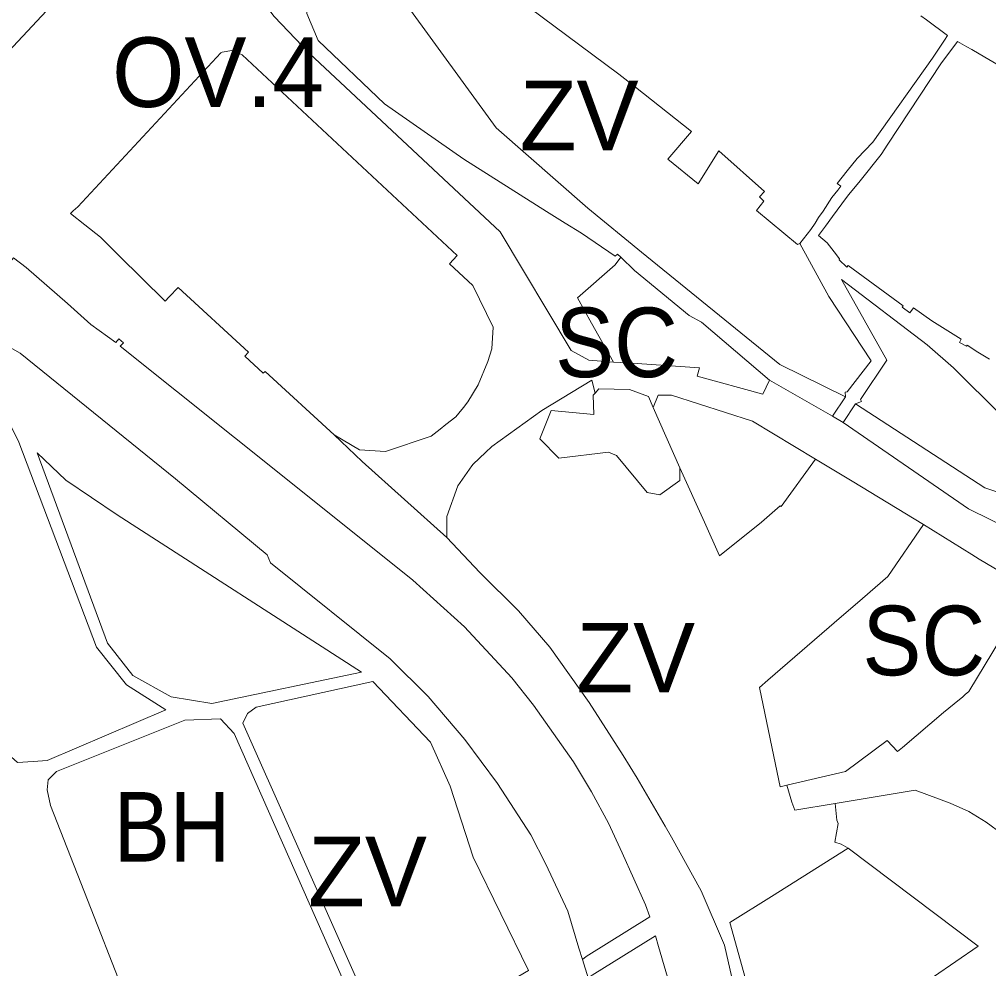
# Model space of a CAD drawing. Extents: x -650451 to -642268, y -1075216 to -1066610.
# Drawn here: x -647355.8 to -647188.6, y -1070735.3 to -1070571.6 of the extents above; entities that cross this region are included whole.
import ezdxf

# ---------------------------------------------------------------- set-up
doc = ezdxf.new("R2010")
doc.units = 0
doc.header["$LTSCALE"] = 4.8
for name, color, linetype, lineweight in [('1', 7, 'Continuous', 13), ('11', 7, 'Continuous', 13), ('15', 7, 'Continuous', 13), ('17', 7, 'Continuous', 13), ('2', 7, 'Continuous', 13), ('40', 7, 'Continuous', 13), ('45', 7, 'Continuous', 13)]:
    doc.layers.add(name, color=color, linetype=linetype, lineweight=lineweight)
doc.layers.add('62', color=7, linetype='Continuous')

msp = doc.modelspace()

# ---------------------------------------------------------------- linework, layer by layer
at = {"layer": '1'}
for points in [[(-647353.37, -1070699.58), (-647356.11, -1070699.76), (-647358.85, -1070697.3), (-647362.45, -1070687.53), (-647369.09, -1070669.52), (-647370.33, -1070666.14), (-647379.3, -1070641.82), (-647378.23, -1070639.17), (-647370.09, -1070629.34), (-647364.48, -1070631.56), (-647359.71, -1070636.82), (-647355.84, -1070644.52), (-647342.44, -1070679.87), (-647337.28, -1070686.33), (-647330.49, -1070690.64), (-647350.95, -1070699.42)], [(-647325.77, -1070770.02), (-647333.28, -1070750.85), (-647334.71, -1070747.19), (-647340.28, -1070732.97), (-647341.72, -1070729.31), (-647350.4, -1070707.16), (-647350.96, -1070704.48), (-647350.8, -1070702.71), (-647349.38, -1070701.29), (-647327.26, -1070692.44), (-647321.09, -1070692.24), (-647318.75, -1070694.72), (-647293.92, -1070750.76)]]:
    msp.add_lwpolyline(points, close=True, dxfattribs=at)
at = {"layer": '11'}
msp.add_lwpolyline([(-647301.47, -1070643.27), (-647313.38, -1070632.31), (-647313.74, -1070632.63), (-647316.87, -1070629.7), (-647316.23, -1070629), (-647328.38, -1070617.87), (-647329.91, -1070619.43), (-647330.65, -1070620.18), (-647338.62, -1070612.33), (-647341.79, -1070609.17), (-647344.5, -1070607.02), (-647346.97, -1070605.07), (-647346.47, -1070604.63), (-647345.68, -1070603.93), (-647321.05, -1070577.4), (-647320.8, -1070577.25), (-647319.1, -1070576.96), (-647318.73, -1070577.12), (-647317.37, -1070577.72), (-647280.26, -1070612.31), (-647281.56, -1070613.76), (-647277.55, -1070617.48), (-647274.07, -1070624.66), (-647274.29, -1070628.4), (-647274.95, -1070630.6), (-647276.66, -1070634.6), (-647278.41, -1070637.55), (-647279.19, -1070638.53), (-647279.99, -1070639.53), (-647280.48, -1070640.15), (-647282.2, -1070641.48), (-647283.2, -1070642.26), (-647284.76, -1070643.47), (-647292.63, -1070646.15), (-647297.09, -1070645.85)], close=True, dxfattribs=at)
for points in [[(-647223.41, -1070703.66), (-647213.3, -1070701.31), (-647206.09, -1070695.93), (-647204.33, -1070697.84), (-647203.49, -1070697.13), (-647196.38, -1070691.15), (-647194.55, -1070689.63), (-647193.07, -1070688.41), (-647192.66, -1070688.03), (-647192.05, -1070687.52), (-647190.53, -1070685.01), (-647188.06, -1070680.95), (-647186.61, -1070678.56), (-647183.3, -1070673.12), (-647181.36, -1070669.94)], [(-647215.09, -1070706.81), (-647222.02, -1070707.98), (-647222.52, -1070706.56), (-647223.41, -1070703.66)], [(-647186.24, -1070712.1), (-647189.06, -1070710.05), (-647192.01, -1070708.17), (-647195.23, -1070706.78), (-647201.28, -1070704.5), (-647215.09, -1070706.81)]]:
    msp.add_lwpolyline(points, dxfattribs=at)
at = {"layer": '15'}
for points in [[(-647359.36, -1070578.94), (-647344.52, -1070563.09), (-647344.36, -1070562.93), (-647343.66, -1070563.58), (-647336.29, -1070555.75), (-647335.69, -1070555.11), (-647336, -1070554.26), (-647346.61, -1070524.59), (-647351.57, -1070510.89), (-647356.57, -1070496.88)], [(-647312.46, -1070553.28), (-647317.15, -1070558.53), (-647317.82, -1070560.19), (-647317.54, -1070562.38), (-647317.15, -1070563.76), (-647315.54, -1070566.13), (-647311.82, -1070571.13), (-647305.74, -1070577.49), (-647272.84, -1070608.27), (-647260.63, -1070628.71), (-647257.54, -1070630.35), (-647253.3, -1070630.72)], [(-647221.14, -1070610.26), (-647219.29, -1070607.85), (-647218.53, -1070606.74), (-647217.96, -1070605.79), (-647217.17, -1070604.69), (-647215.63, -1070602.35), (-647214.6, -1070601.09), (-647214.11, -1070600.39), (-647214.72, -1070599.93), (-647212.98, -1070597.76), (-647211.27, -1070595.62), (-647208.55, -1070592.81), (-647198.31, -1070578.28), (-647196.23, -1070575.2), (-647195.7, -1070574.42), (-647199.34, -1070571.72), (-647200.3, -1070571.01)], [(-647185.4, -1070580.35), (-647189.29, -1070578.11), (-647191.52, -1070576.82), (-647192.34, -1070576.35), (-647193.96, -1070575.45), (-647196.84, -1070579.31), (-647205.98, -1070593.12), (-647207.14, -1070594.94), (-647210.79, -1070599.46), (-647212.69, -1070601.8), (-647213.13, -1070602.35), (-647215.54, -1070605.62), (-647216.75, -1070607.27), (-647217.95, -1070608.9), (-647216.43, -1070610.17), (-647215.24, -1070611.71), (-647214.33, -1070612.9), (-647214.39, -1070613.09), (-647213.05, -1070614.33), (-647212.85, -1070614.07), (-647203.32, -1070620.99), (-647203.51, -1070621.22), (-647202.2, -1070622.2), (-647201.54, -1070621.37), (-647198.43, -1070623.59), (-647193.35, -1070626.75), (-647193.61, -1070627.33), (-647192.44, -1070627.96), (-647192.3, -1070627.78), (-647190.45, -1070628.98), (-647188.43, -1070630.2)], [(-647213.29, -1070636.7), (-647213.37, -1070635.89), (-647213, -1070635.85), (-647208.87, -1070630.47), (-647216.16, -1070619.38), (-647221.14, -1070610.26)], [(-647356.77, -1070612.71), (-647364.72, -1070622.59), (-647357.74, -1070627.98), (-647355.61, -1070629.17), (-647328.85, -1070650.84), (-647313.05, -1070663.93), (-647312.47, -1070665.3), (-647291.8, -1070681.86), (-647285.28, -1070688.36), (-647278.93, -1070695.8), (-647273.3, -1070703.37), (-647267.58, -1070712.21), (-647264.99, -1070717.25), (-647261.17, -1070725.4), (-647259.26, -1070731.73), (-647258.66, -1070733.71), (-647257.7, -1070736.849)], [(-647258.66, -1070733.71), (-647258.02, -1070733.2), (-647247.02, -1070726.38), (-647247.76, -1070724.31), (-647251.79, -1070715.3), (-647254.17, -1070710.2), (-647257.09, -1070704.81), (-647260.2, -1070699.65), (-647267.08, -1070689.85), (-647270.82, -1070685.13), (-647278.98, -1070676.34), (-647287.92, -1070668.32), (-647308.93, -1070651.44), (-647338.37, -1070627.96), (-647337.81, -1070627.4), (-647338.61, -1070626.72), (-647339.15, -1070627.35), (-647343.45, -1070624.25), (-647347.45, -1070620.61), (-647354.58, -1070614.42), (-647356.77, -1070612.71)], [(-647170.16, -1070644.59), (-647172.63, -1070643.88), (-647186.4, -1070639.91), (-647194.67, -1070631.67), (-647199.19, -1070627.76), (-647213.98, -1070616.48), (-647206.19, -1070630.4), (-647210.68, -1070637.17), (-647210.52, -1070637.52), (-647211.57, -1070637.9), (-647213.68, -1070641.13), (-647215.55, -1070640.03), (-647213.29, -1070636.7)], [(-647253.3, -1070630.72), (-647250.87, -1070630.83), (-647238.45, -1070631.69), (-647238.85, -1070633.11), (-647227.54, -1070636.24), (-647226.39, -1070633.82), (-647215.55, -1070640.03), (-647213.68, -1070641.13)], [(-647256.46, -1070636.04), (-647257.03, -1070633.8), (-647265.65, -1070639.04), (-647274.26, -1070645.27), (-647275.35, -1070646.3), (-647277.51, -1070648.32), (-647277.72, -1070648.62), (-647280.13, -1070652.04), (-647282.03, -1070657.35), (-647282.03, -1070660.97)], [(-647246.49, -1070638.53), (-647247.27, -1070636.62), (-647250.55, -1070635.45), (-647255.81, -1070635.34), (-647256.46, -1070636.04)], [(-647218.44, -1070647.43), (-647229.34, -1070640.91), (-647243.28, -1070636.43), (-647245.6, -1070636.4), (-647246.49, -1070638.53)], [(-647213.68, -1070641.13), (-647192.07, -1070655.98), (-647168.72, -1070667.48), (-647167.98, -1070665.84), (-647155.28, -1070670.24), (-647153.1, -1070667.29), (-647148.15, -1070669.49), (-647150.25, -1070671.84)], [(-647282.03, -1070660.97), (-647296.63, -1070647.83), (-647301.47, -1070643.27)], [(-647301.47, -1070643.27), (-647296.63, -1070647.83), (-647282.03, -1070660.97)], [(-647199.86, -1070658.73), (-647212.15, -1070651.26), (-647218.44, -1070647.43)], [(-647181.36, -1070669.94), (-647184.22, -1070668.24), (-647190.22, -1070664.68), (-647191.53, -1070663.9), (-647199.86, -1070658.73)], [(-647282.03, -1070660.97), (-647276.33, -1070666.98), (-647269.7, -1070673.6), (-647264.28, -1070679.85), (-647257.5, -1070689.42), (-647251.65, -1070698.54), (-647249.24, -1070702.45), (-647244.42, -1070710.72), (-647243.32, -1070712.61), (-647238.17, -1070721.85), (-647234.15, -1070731.23), (-647232.04, -1070740.63), (-647230.91, -1070759.64), (-647232.98, -1070796.15)], [(-647234.692, -1070915.011), (-647224.85, -1070903.83), (-647230.18, -1070895.42), (-647234.96, -1070886.44), (-647239.25, -1070875.22), (-647242.25, -1070862.17), (-647243.66, -1070845.66), (-647239.62, -1070773.47), (-647239.86, -1070761.48), (-647241.3, -1070749.53), (-647241.85, -1070745.57), (-647240.98, -1070745.38), (-647241.85, -1070740.97), (-647242.7, -1070741.08), (-647245.52, -1070731.47), (-647246.06, -1070729.62), (-647257.01, -1070736.43), (-647257.7, -1070736.849), (-647258.66, -1070733.71)]]:
    msp.add_lwpolyline(points, dxfattribs=at)
for points in [[(-647301.47, -1070643.27), (-647297.09, -1070645.85), (-647292.63, -1070646.15), (-647284.76, -1070643.47), (-647283.2, -1070642.26), (-647282.2, -1070641.48), (-647280.48, -1070640.15), (-647279.99, -1070639.53), (-647279.19, -1070638.53), (-647278.41, -1070637.55), (-647276.66, -1070634.6), (-647274.95, -1070630.6), (-647274.29, -1070628.4), (-647274.07, -1070624.66), (-647277.55, -1070617.48), (-647281.56, -1070613.76), (-647280.26, -1070612.31), (-647317.37, -1070577.72), (-647318.73, -1070577.12), (-647319.1, -1070576.96), (-647320.8, -1070577.25), (-647321.05, -1070577.4), (-647345.68, -1070603.93), (-647346.47, -1070604.63), (-647346.97, -1070605.07), (-647344.5, -1070607.02), (-647341.79, -1070609.17), (-647338.62, -1070612.33), (-647330.65, -1070620.18), (-647329.91, -1070619.43), (-647328.38, -1070617.87), (-647316.23, -1070629), (-647316.87, -1070629.7), (-647313.74, -1070632.63), (-647313.38, -1070632.31)], [(-647353.37, -1070699.58), (-647350.95, -1070699.42), (-647330.49, -1070690.64), (-647337.28, -1070686.33), (-647342.44, -1070679.87), (-647355.84, -1070644.52), (-647359.71, -1070636.82), (-647364.48, -1070631.56), (-647370.09, -1070629.34), (-647378.23, -1070639.17), (-647379.3, -1070641.82), (-647370.33, -1070666.14), (-647369.09, -1070669.52), (-647362.45, -1070687.53), (-647358.85, -1070697.3), (-647356.11, -1070699.76)], [(-647296.74, -1070684.19), (-647338.92, -1070657.07), (-647347.73, -1070651.08), (-647352.71, -1070646.37), (-647340.54, -1070679.18), (-647336.21, -1070684.77), (-647329.61, -1070688.42), (-647322.6, -1070689.56)], [(-647267.95, -1070735.6), (-647277.48, -1070716.04), (-647281.45, -1070703.81), (-647284.89, -1070696.22), (-647294.81, -1070685.78), (-647314.95, -1070690.19), (-647316.43, -1070691.27), (-647317.24, -1070692.98), (-647291.98, -1070749.68)], [(-647325.77, -1070770.02), (-647293.92, -1070750.76), (-647318.75, -1070694.72), (-647321.09, -1070692.24), (-647327.26, -1070692.44), (-647349.38, -1070701.29), (-647350.8, -1070702.71), (-647350.96, -1070704.48), (-647350.4, -1070707.16), (-647341.72, -1070729.31), (-647340.28, -1070732.97), (-647334.71, -1070747.19), (-647333.28, -1070750.85)]]:
    msp.add_lwpolyline(points, close=True, dxfattribs=at)
at = {"layer": '17'}
for points in [[(-647356.57, -1070496.88), (-647351.57, -1070510.89), (-647346.61, -1070524.59), (-647336, -1070554.26), (-647335.69, -1070555.11), (-647336.29, -1070555.75), (-647343.66, -1070563.58), (-647344.36, -1070562.93), (-647344.52, -1070563.09), (-647359.36, -1070578.94)], [(-647221.14, -1070610.26), (-647221.58, -1070610.41), (-647228.64, -1070604.58), (-647227.36, -1070602.95), (-647228.11, -1070602.21), (-647227.29, -1070601.29), (-647235.16, -1070594.29), (-647238.73, -1070599.96), (-647243.96, -1070595.7), (-647239.85, -1070590.97), (-647249.52, -1070583.31), (-647252.39, -1070581.07), (-647274.56, -1070564.5)], [(-647200.3, -1070571.01), (-647199.34, -1070571.72), (-647195.7, -1070574.42), (-647196.23, -1070575.2), (-647198.31, -1070578.28), (-647208.55, -1070592.81), (-647211.27, -1070595.62), (-647212.98, -1070597.76), (-647214.72, -1070599.93), (-647214.11, -1070600.39), (-647214.6, -1070601.09), (-647215.63, -1070602.35), (-647217.17, -1070604.69), (-647217.96, -1070605.79), (-647218.53, -1070606.74), (-647219.29, -1070607.85), (-647221.14, -1070610.26)], [(-647188.43, -1070630.2), (-647190.45, -1070628.98), (-647192.3, -1070627.78), (-647192.44, -1070627.96), (-647193.61, -1070627.33), (-647193.35, -1070626.75), (-647198.43, -1070623.59), (-647201.54, -1070621.37), (-647202.2, -1070622.2), (-647203.51, -1070621.22), (-647203.32, -1070620.99), (-647212.85, -1070614.07), (-647213.05, -1070614.33), (-647214.39, -1070613.09), (-647214.33, -1070612.9), (-647215.24, -1070611.71), (-647216.43, -1070610.17), (-647217.95, -1070608.9), (-647216.75, -1070607.27), (-647215.54, -1070605.62), (-647213.13, -1070602.35), (-647212.69, -1070601.8), (-647210.79, -1070599.46), (-647207.14, -1070594.94), (-647205.98, -1070593.12), (-647196.84, -1070579.31), (-647193.96, -1070575.45), (-647192.34, -1070576.35), (-647191.52, -1070576.82), (-647189.29, -1070578.11), (-647185.4, -1070580.35)], [(-647253.3, -1070630.72), (-647257.07, -1070624), (-647259.53, -1070619.63), (-647253.03, -1070613.91), (-647252.04, -1070612.62)], [(-647252.04, -1070612.62), (-647249.7, -1070614.89), (-647240.25, -1070622.65), (-647238.12, -1070623.8), (-647226.39, -1070633.82)], [(-647226.39, -1070633.82), (-647227.54, -1070636.24), (-647238.85, -1070633.11), (-647238.45, -1070631.69), (-647250.87, -1070630.83), (-647253.3, -1070630.72)], [(-647246.49, -1070638.53), (-647245.6, -1070636.4), (-647243.28, -1070636.43), (-647229.34, -1070640.91), (-647218.44, -1070647.43)], [(-647218.44, -1070647.43), (-647224.37, -1070655.59), (-647224.57, -1070655.48), (-647227.76, -1070658.33), (-647235.02, -1070664.1), (-647237.61, -1070658.33), (-647241.89, -1070648.94), (-647246.49, -1070638.53)], [(-647223.41, -1070703.66), (-647224.55, -1070703.92), (-647225.35, -1070700.1), (-647228.14, -1070686.83), (-647226.67, -1070685.57), (-647213.96, -1070674.56), (-647211.22, -1070672.21), (-647210.36, -1070671.47), (-647206.02, -1070667.69), (-647199.86, -1070658.73)], [(-647199.86, -1070658.73), (-647191.53, -1070663.9), (-647190.22, -1070664.68), (-647184.22, -1070668.24), (-647181.36, -1070669.94)], [(-647181.36, -1070669.94), (-647183.3, -1070673.12), (-647186.61, -1070678.56), (-647188.06, -1070680.95), (-647190.53, -1070685.01), (-647192.05, -1070687.52), (-647192.66, -1070688.03), (-647193.07, -1070688.41), (-647194.55, -1070689.63), (-647196.38, -1070691.15), (-647203.49, -1070697.13), (-647204.33, -1070697.84), (-647206.09, -1070695.93), (-647213.3, -1070701.31), (-647223.41, -1070703.66)], [(-647215.09, -1070706.81), (-647201.28, -1070704.5), (-647195.23, -1070706.78), (-647192.01, -1070708.17), (-647189.06, -1070710.05), (-647186.24, -1070712.1)], [(-647212.86, -1070714.53), (-647214.06, -1070713.83), (-647215.15, -1070713.48), (-647214.53, -1070710.27), (-647214.8, -1070709.66), (-647215.09, -1070706.81)], [(-647236.44, -1070835.13), (-647232.78, -1070836.22), (-647211.44, -1070842.62), (-647207.55, -1070836.46), (-647212.27, -1070833.64), (-647209.5, -1070829), (-647204.6, -1070817.33), (-647201.97, -1070813.55), (-647209.67, -1070797.53), (-647200.88, -1070786.23), (-647200.9, -1070785.57), (-647198.85, -1070785.66), (-647199.54, -1070780.04), (-647199.97, -1070773.61), (-647200.04, -1070772.52), (-647199.38, -1070763.7), (-647200.89, -1070751.29), (-647202.89, -1070747.79), (-647203.21, -1070744.98), (-647206.67, -1070742.46), (-647198.12, -1070736.68), (-647190.41, -1070731.4), (-647212.86, -1070714.53)]]:
    msp.add_lwpolyline(points, dxfattribs=at)
at = {"layer": '2'}
for points in [[(-647212.86, -1070714.53), (-647190.41, -1070731.4), (-647198.12, -1070736.68), (-647206.67, -1070742.46), (-647203.21, -1070744.98), (-647202.89, -1070747.79), (-647200.89, -1070751.29), (-647199.38, -1070763.7), (-647200.04, -1070772.52), (-647199.97, -1070773.61), (-647199.54, -1070780.04), (-647198.85, -1070785.66), (-647200.9, -1070785.57), (-647200.88, -1070786.23), (-647209.67, -1070797.53), (-647201.97, -1070813.55), (-647204.6, -1070817.33), (-647209.5, -1070829), (-647212.27, -1070833.64), (-647207.55, -1070836.46), (-647211.44, -1070842.62), (-647232.78, -1070836.22), (-647236.44, -1070835.13)], [(-647232.98, -1070796.15), (-647230.79, -1070796.17), (-647230.48, -1070796.18), (-647229.81, -1070784.01), (-647229.2, -1070772.02), (-647228.38, -1070759.67), (-647227.57, -1070747.79), (-647233.26, -1070727.35), (-647226.05, -1070722.86), (-647212.86, -1070714.53)]]:
    msp.add_lwpolyline(points, dxfattribs=at)
at = {"layer": '40'}
for points in [[(-647213.29, -1070636.7), (-647224.62, -1070631.13), (-647248.47, -1070611.77), (-647257.72, -1070604.16), (-647273.54, -1070590.32), (-647289.23, -1070568.74), (-647294.04, -1070557.72), (-647299.94, -1070539.82), (-647309.17, -1070504.84)], [(-647253.3, -1070630.72), (-647257.54, -1070630.35), (-647260.63, -1070628.71), (-647272.84, -1070608.27), (-647305.74, -1070577.49), (-647311.82, -1070571.13), (-647315.54, -1070566.13), (-647317.15, -1070563.76), (-647317.54, -1070562.38), (-647317.82, -1070560.19), (-647317.15, -1070558.53), (-647312.46, -1070553.28)], [(-647312.46, -1070553.28), (-647307.04, -1070558.96), (-647306.21, -1070570.58), (-647304.24, -1070575.28), (-647292.78, -1070586.17), (-647279.11, -1070595.72), (-647264.84, -1070604.72), (-647261.65, -1070606.73), (-647258.83, -1070608.49), (-647253.03, -1070612.42), (-647252.64, -1070612.08), (-647252.04, -1070612.62)], [(-647274.56, -1070564.5), (-647252.39, -1070581.07), (-647249.52, -1070583.31), (-647239.85, -1070590.97), (-647243.96, -1070595.7), (-647238.73, -1070599.96), (-647235.16, -1070594.29), (-647227.29, -1070601.29), (-647228.11, -1070602.21), (-647227.36, -1070602.95), (-647228.64, -1070604.58), (-647221.58, -1070610.41), (-647221.14, -1070610.26)], [(-647221.14, -1070610.26), (-647216.16, -1070619.38), (-647208.87, -1070630.47), (-647213, -1070635.85), (-647213.37, -1070635.89), (-647213.29, -1070636.7)], [(-647252.04, -1070612.62), (-647253.03, -1070613.91), (-647259.53, -1070619.63), (-647257.07, -1070624), (-647253.3, -1070630.72)], [(-647211.57, -1070637.9), (-647210.52, -1070637.52), (-647210.68, -1070637.17), (-647206.19, -1070630.4), (-647213.98, -1070616.48), (-647199.19, -1070627.76), (-647194.67, -1070631.67), (-647186.4, -1070639.91), (-647172.63, -1070643.88), (-647170.16, -1070644.59)], [(-647282.03, -1070660.97), (-647282.03, -1070657.35), (-647280.13, -1070652.04), (-647277.72, -1070648.62), (-647277.51, -1070648.32), (-647275.35, -1070646.3), (-647274.26, -1070645.27), (-647265.65, -1070639.04), (-647257.03, -1070633.8), (-647256.46, -1070636.04)], [(-647256.46, -1070636.04), (-647256.83, -1070636.43), (-647256.68, -1070639.73), (-647264.03, -1070639.08), (-647265.98, -1070643.95), (-647262.73, -1070647.29), (-647254.19, -1070646.22), (-647252.77, -1070646.84), (-647247.51, -1070653.21), (-647245.29, -1070653.59), (-647241.87, -1070651.11), (-647241.89, -1070648.94)], [(-647175.83, -1070656.89), (-647189.25, -1070652.4), (-647211.57, -1070637.9)], [(-647241.89, -1070648.94), (-647237.61, -1070658.33), (-647235.02, -1070664.1), (-647227.76, -1070658.33), (-647224.57, -1070655.48), (-647224.37, -1070655.59), (-647218.44, -1070647.43)], [(-647218.44, -1070647.43), (-647212.15, -1070651.26), (-647199.86, -1070658.73)], [(-647199.86, -1070658.73), (-647206.02, -1070667.69), (-647210.36, -1070671.47), (-647211.22, -1070672.21), (-647213.96, -1070674.56), (-647226.67, -1070685.57), (-647228.14, -1070686.83), (-647225.35, -1070700.1), (-647224.55, -1070703.92), (-647223.41, -1070703.66)], [(-647232.98, -1070796.15), (-647230.91, -1070759.64), (-647232.04, -1070740.63), (-647234.15, -1070731.23), (-647238.17, -1070721.85), (-647243.32, -1070712.61), (-647244.42, -1070710.72), (-647249.24, -1070702.45), (-647251.65, -1070698.54), (-647257.5, -1070689.42), (-647264.28, -1070679.85), (-647269.7, -1070673.6), (-647276.33, -1070666.98), (-647282.03, -1070660.97)], [(-647223.41, -1070703.66), (-647222.52, -1070706.56), (-647222.02, -1070707.98), (-647215.09, -1070706.81)], [(-647215.09, -1070706.81), (-647214.8, -1070709.66), (-647214.53, -1070710.27), (-647215.15, -1070713.48), (-647214.06, -1070713.83), (-647212.86, -1070714.53)], [(-647212.86, -1070714.53), (-647226.05, -1070722.86), (-647233.26, -1070727.35), (-647227.57, -1070747.79), (-647228.38, -1070759.67), (-647229.2, -1070772.02), (-647229.81, -1070784.01), (-647230.48, -1070796.18), (-647230.79, -1070796.17), (-647232.98, -1070796.15)]]:
    msp.add_lwpolyline(points, dxfattribs=at)
for points in [[(-647296.74, -1070684.19), (-647322.6, -1070689.56), (-647329.61, -1070688.42), (-647336.21, -1070684.77), (-647340.54, -1070679.18), (-647352.71, -1070646.37), (-647347.73, -1070651.08), (-647338.92, -1070657.07)], [(-647267.95, -1070735.6), (-647291.98, -1070749.68), (-647317.24, -1070692.98), (-647316.43, -1070691.27), (-647314.95, -1070690.19), (-647294.81, -1070685.78), (-647284.89, -1070696.22), (-647281.45, -1070703.81), (-647277.48, -1070716.04)]]:
    msp.add_lwpolyline(points, close=True, dxfattribs=at)
at = {"layer": '45'}
msp.add_line((-647213.68, -1070641.13), (-647211.57, -1070637.9), dxfattribs=at)
for points in [[(-647309.17, -1070504.84), (-647299.94, -1070539.82), (-647294.04, -1070557.72), (-647289.23, -1070568.74), (-647273.54, -1070590.32), (-647257.72, -1070604.16), (-647248.47, -1070611.77), (-647224.62, -1070631.13), (-647213.29, -1070636.7), (-647215.55, -1070640.03), (-647226.39, -1070633.82)], [(-647252.04, -1070612.62), (-647252.64, -1070612.08), (-647253.03, -1070612.42), (-647258.83, -1070608.49), (-647261.65, -1070606.73), (-647264.84, -1070604.72), (-647279.11, -1070595.72), (-647292.78, -1070586.17), (-647304.24, -1070575.28), (-647306.21, -1070570.58), (-647307.04, -1070558.96), (-647312.46, -1070553.28)], [(-647258.66, -1070733.71), (-647259.26, -1070731.73), (-647261.17, -1070725.4), (-647264.99, -1070717.25), (-647267.58, -1070712.21), (-647273.3, -1070703.37), (-647278.93, -1070695.8), (-647285.28, -1070688.36), (-647291.8, -1070681.86), (-647312.47, -1070665.3), (-647313.05, -1070663.93), (-647328.85, -1070650.84), (-647355.61, -1070629.17), (-647357.74, -1070627.98), (-647364.72, -1070622.59), (-647356.77, -1070612.71)], [(-647356.77, -1070612.71), (-647354.58, -1070614.42), (-647347.45, -1070620.61), (-647343.45, -1070624.25), (-647339.15, -1070627.35), (-647338.61, -1070626.72), (-647337.81, -1070627.4), (-647338.37, -1070627.96), (-647308.93, -1070651.44), (-647287.92, -1070668.32), (-647278.98, -1070676.34), (-647270.82, -1070685.13), (-647267.08, -1070689.85), (-647260.2, -1070699.65), (-647257.09, -1070704.81), (-647254.17, -1070710.2), (-647251.79, -1070715.3), (-647247.76, -1070724.31), (-647247.02, -1070726.38), (-647258.02, -1070733.2), (-647258.66, -1070733.71)], [(-647226.39, -1070633.82), (-647238.12, -1070623.8), (-647240.25, -1070622.65), (-647249.7, -1070614.89), (-647252.04, -1070612.62)], [(-647256.46, -1070636.04), (-647255.81, -1070635.34), (-647250.55, -1070635.45), (-647247.27, -1070636.62), (-647246.49, -1070638.53), (-647241.89, -1070648.94)], [(-647241.89, -1070648.94), (-647241.87, -1070651.11), (-647245.29, -1070653.59), (-647247.51, -1070653.21), (-647252.77, -1070646.84), (-647254.19, -1070646.22), (-647262.73, -1070647.29), (-647265.98, -1070643.95), (-647264.03, -1070639.08), (-647256.68, -1070639.73), (-647256.83, -1070636.43), (-647256.46, -1070636.04)], [(-647211.57, -1070637.9), (-647189.25, -1070652.4), (-647175.83, -1070656.89)], [(-647153.1, -1070667.29), (-647155.28, -1070670.24), (-647167.98, -1070665.84), (-647168.72, -1070667.48), (-647192.07, -1070655.98), (-647213.68, -1070641.13)], [(-647257.7, -1070736.849), (-647257.01, -1070736.43), (-647246.06, -1070729.62), (-647245.52, -1070731.47), (-647242.7, -1070741.08), (-647241.85, -1070740.97), (-647240.98, -1070745.38), (-647241.85, -1070745.57), (-647241.3, -1070749.53), (-647239.86, -1070761.48), (-647239.62, -1070773.47), (-647243.66, -1070845.66), (-647242.25, -1070862.17), (-647239.25, -1070875.22), (-647234.96, -1070886.44), (-647230.18, -1070895.42), (-647224.85, -1070903.83), (-647234.692, -1070915.011)]]:
    msp.add_lwpolyline(points, dxfattribs=at)

# ---------------------------------------------------------------- texts
at = {"layer": '62'}
for s, p in [('OV.4', (-647339.784, -1070586.727)), ('ZV', (-647269.476, -1070594.201)), ('ZV', (-647259.727, -1070687.663)), ('ZV', (-647305.983, -1070724.531))]:
    msp.add_text(s, height=12, dxfattribs=at).set_placement(p)
for s, width, p in [('SC', 0.95, (-647263.371, -1070633.305)), ('SC', 0.95, (-647210.377, -1070684.711)), ('BH', 0.9, (-647339.47, -1070716.825))]:
    msp.add_text(s, height=12, dxfattribs=dict(at, width=width)).set_placement(p)

doc.saveas('drawing.dxf')
